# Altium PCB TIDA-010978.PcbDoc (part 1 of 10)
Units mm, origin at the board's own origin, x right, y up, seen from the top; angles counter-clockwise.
Board outline 243.95 x 94.85 mm, 4 copper layers (Top Layer, Mid Layer 1, Mid Layer 2, Bottom Layer), stack 1.623 mm thick; 865 components, 374 nets, 2308 pads, 2132 vias.
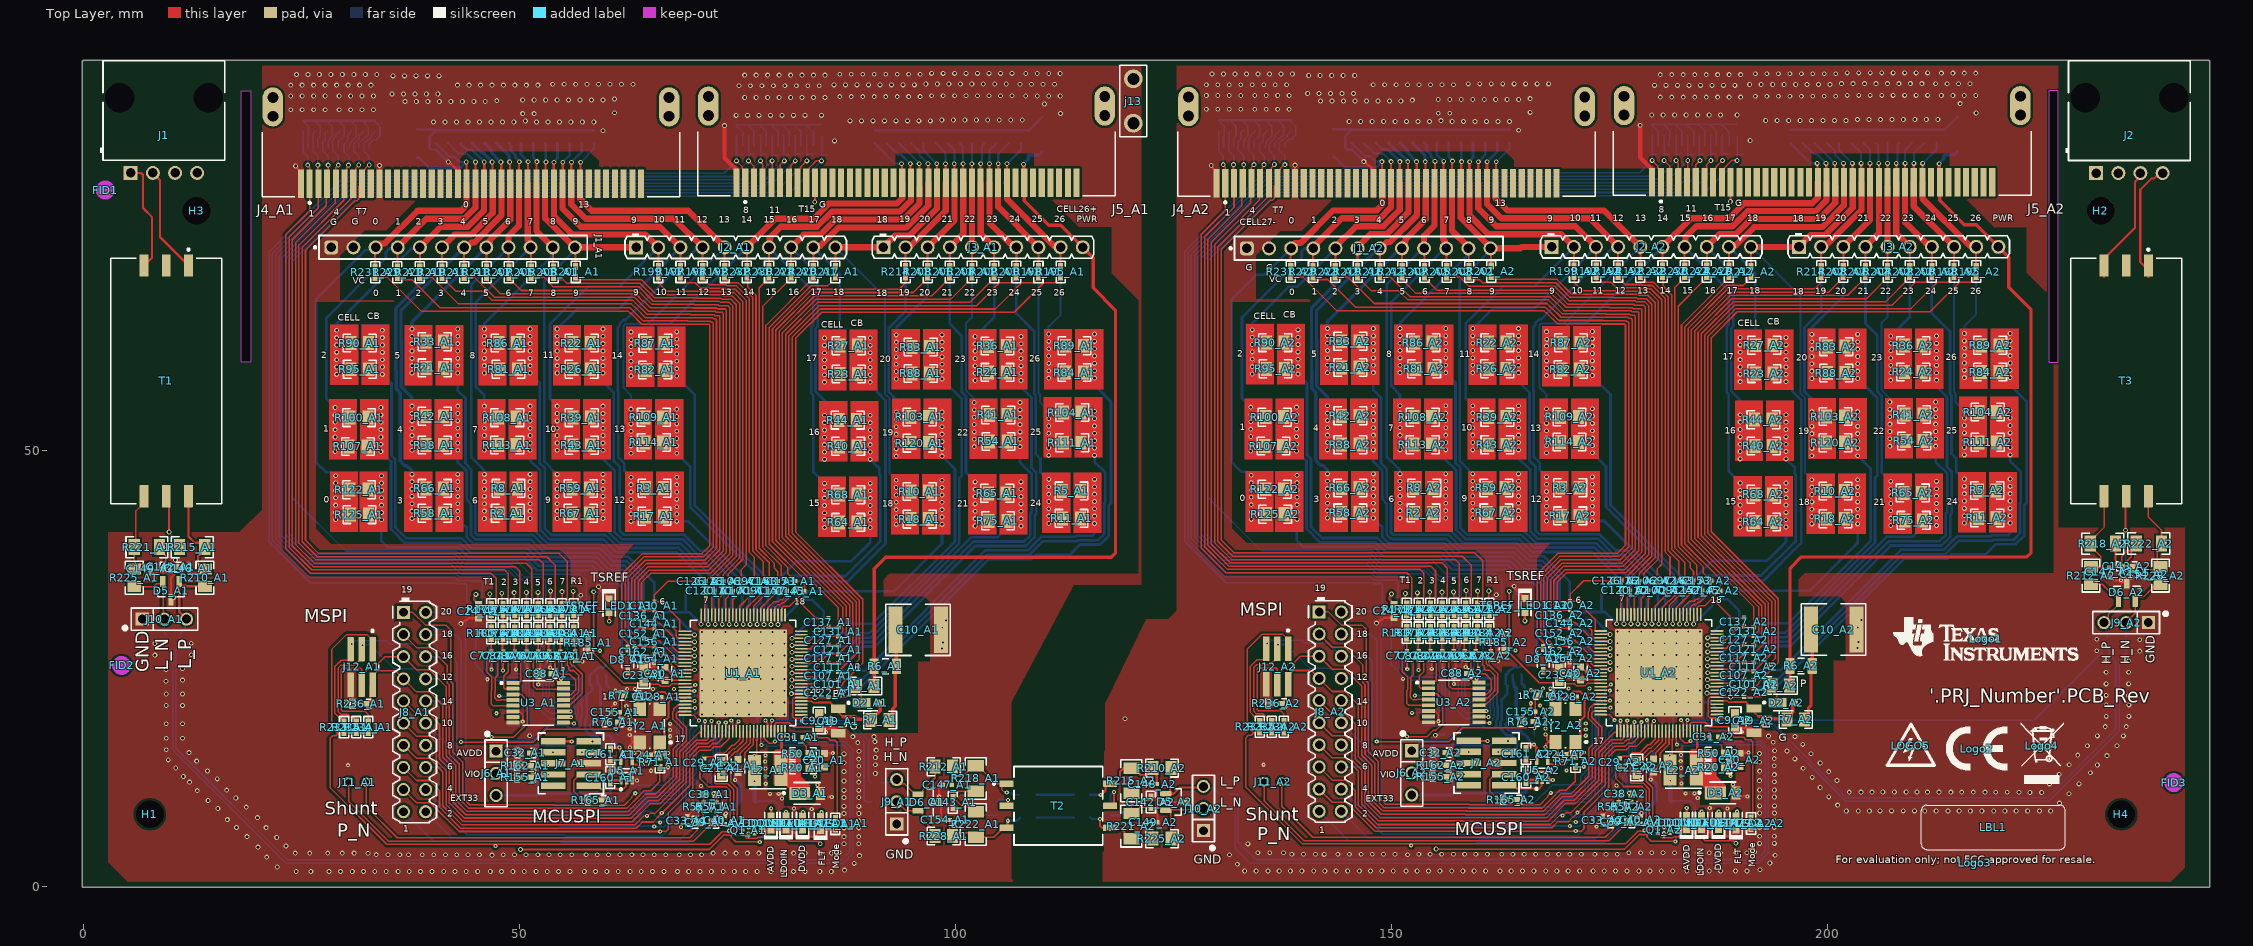
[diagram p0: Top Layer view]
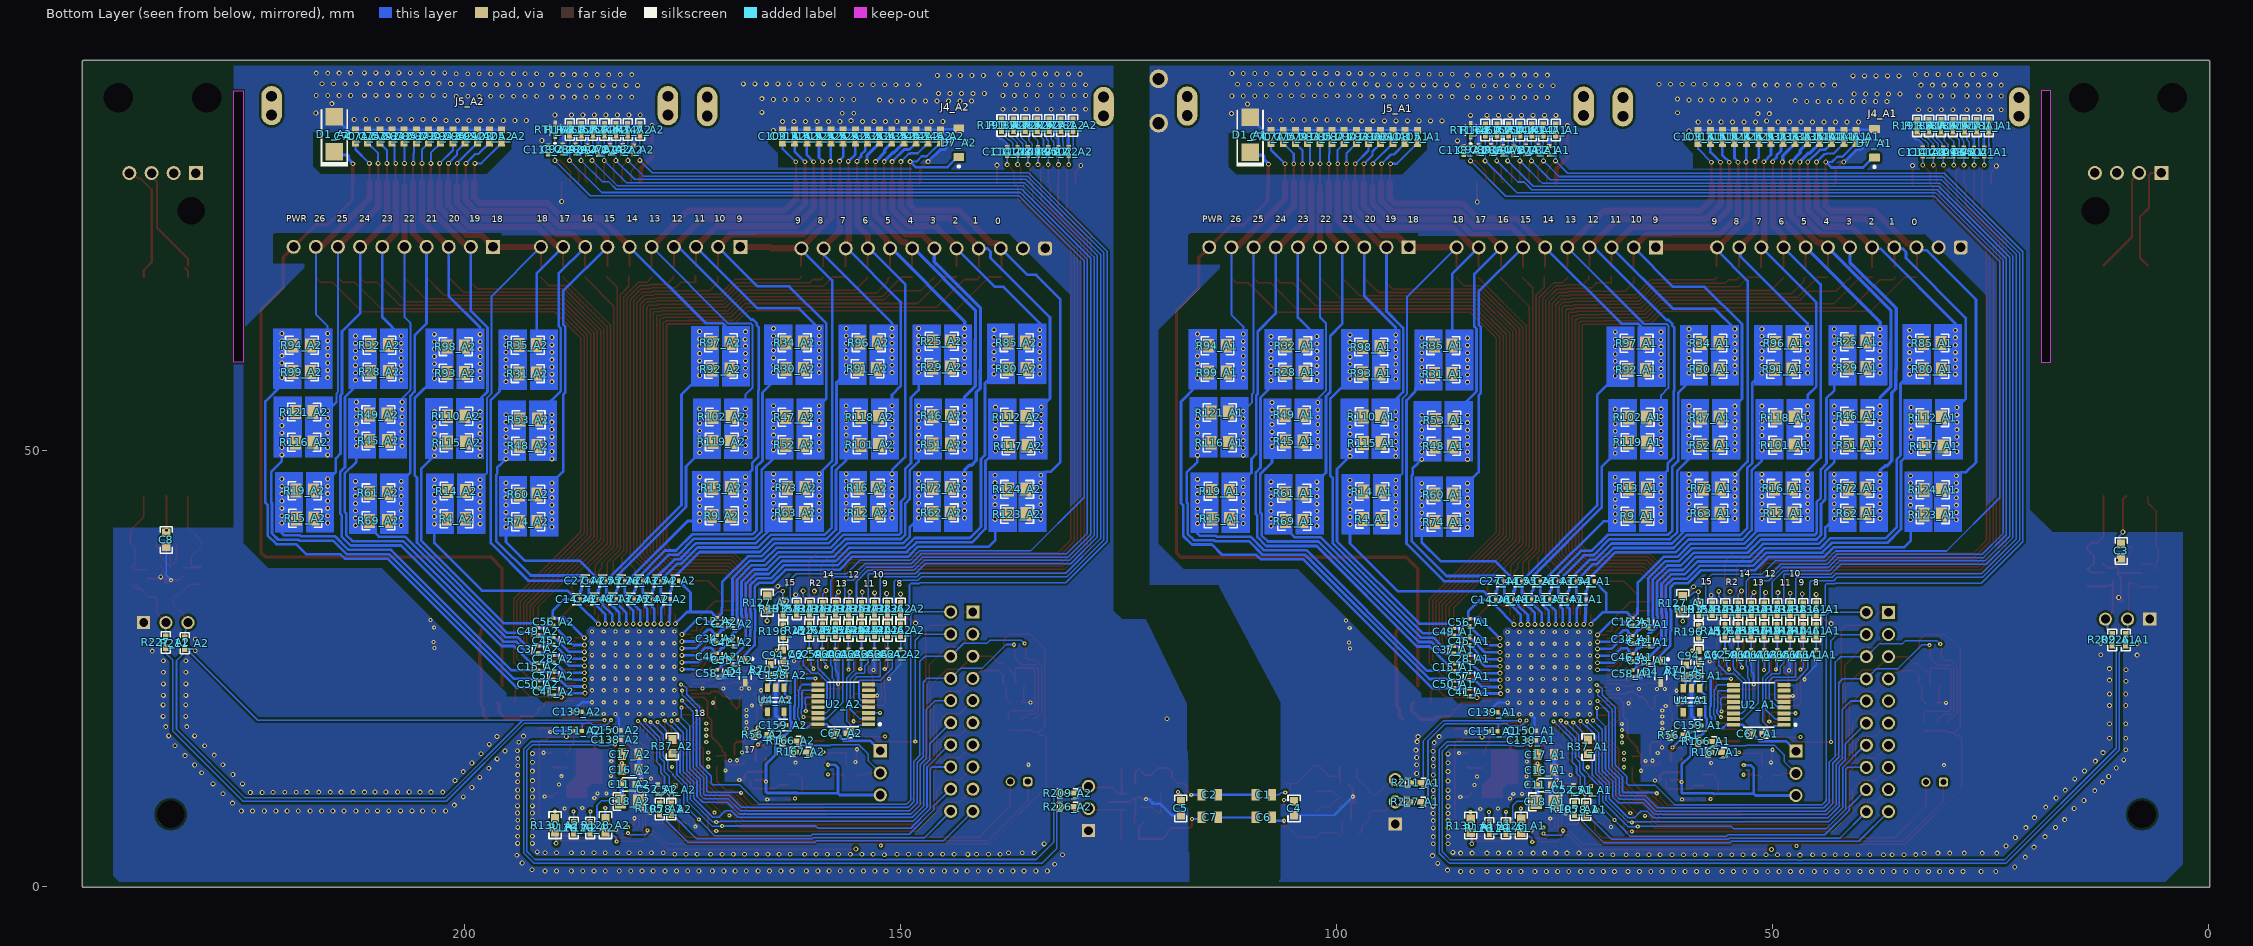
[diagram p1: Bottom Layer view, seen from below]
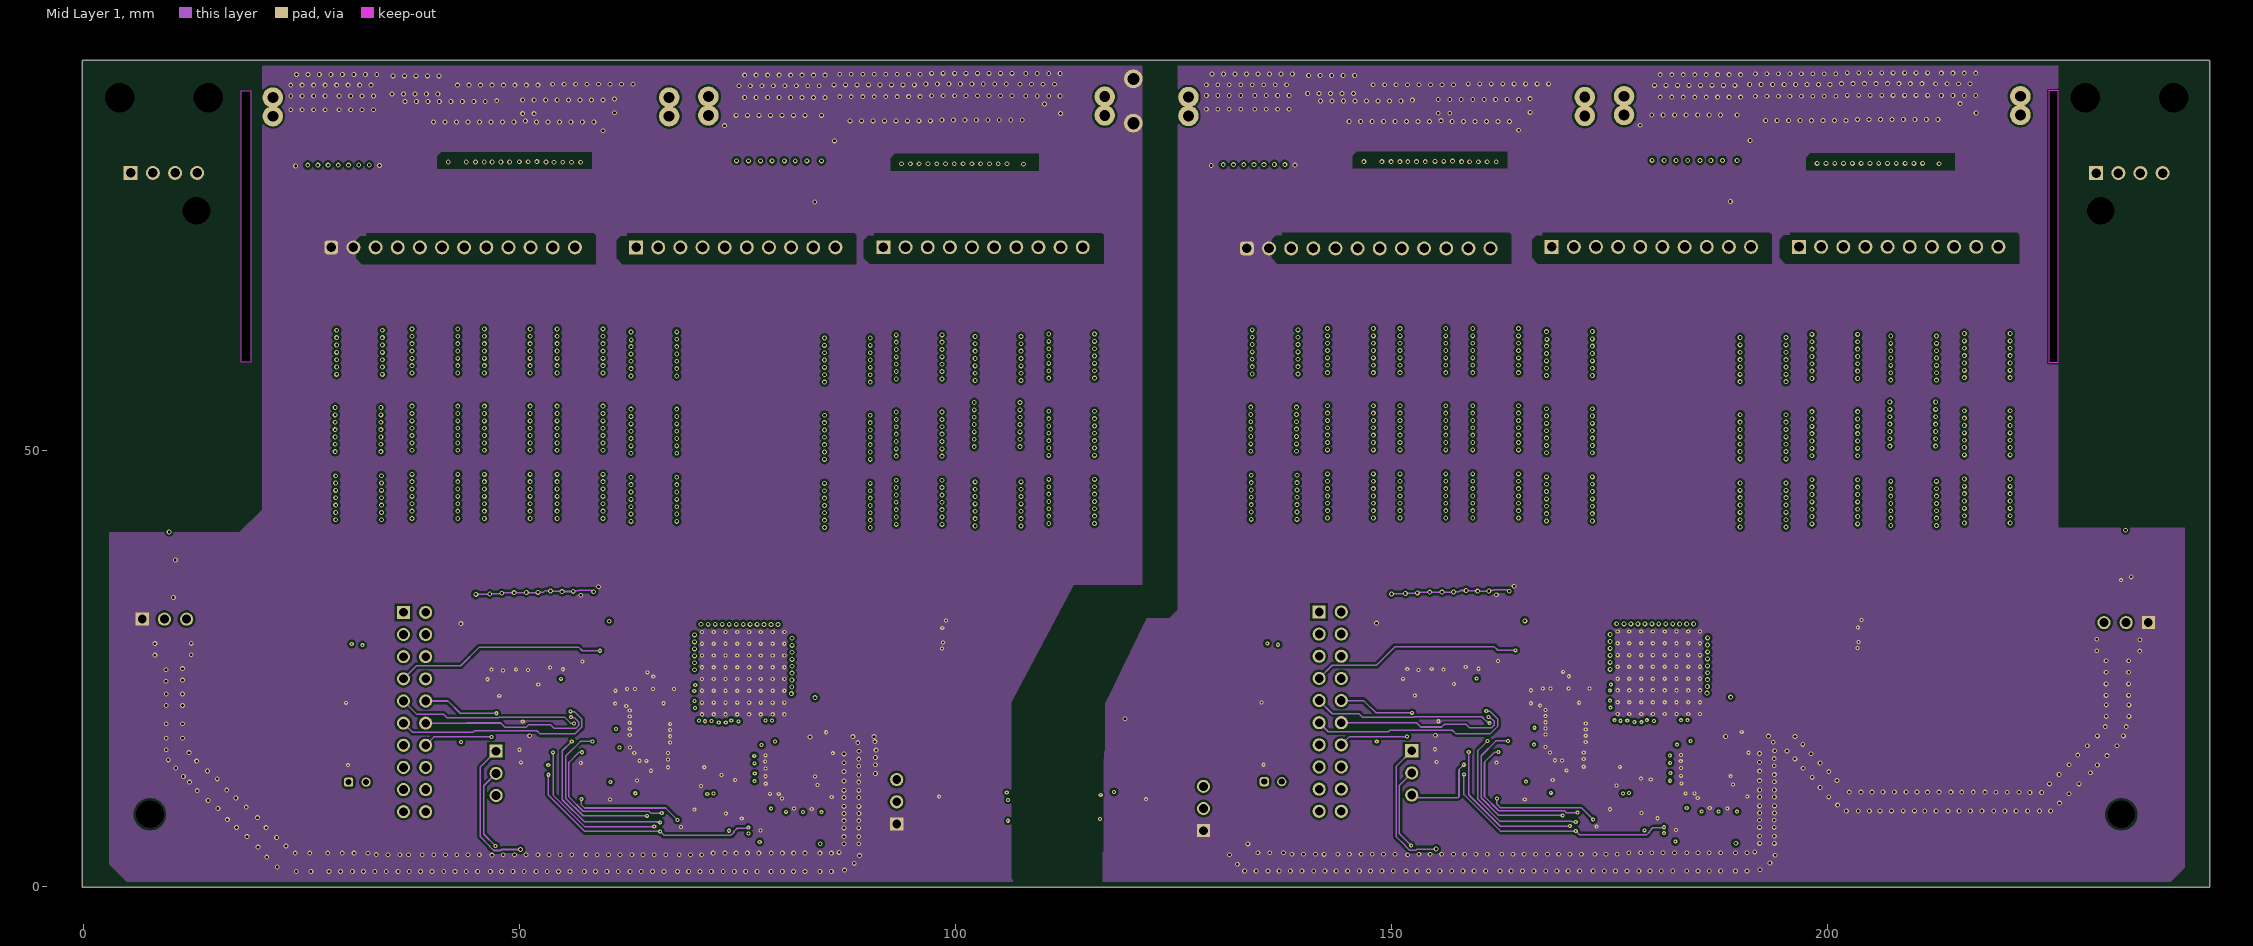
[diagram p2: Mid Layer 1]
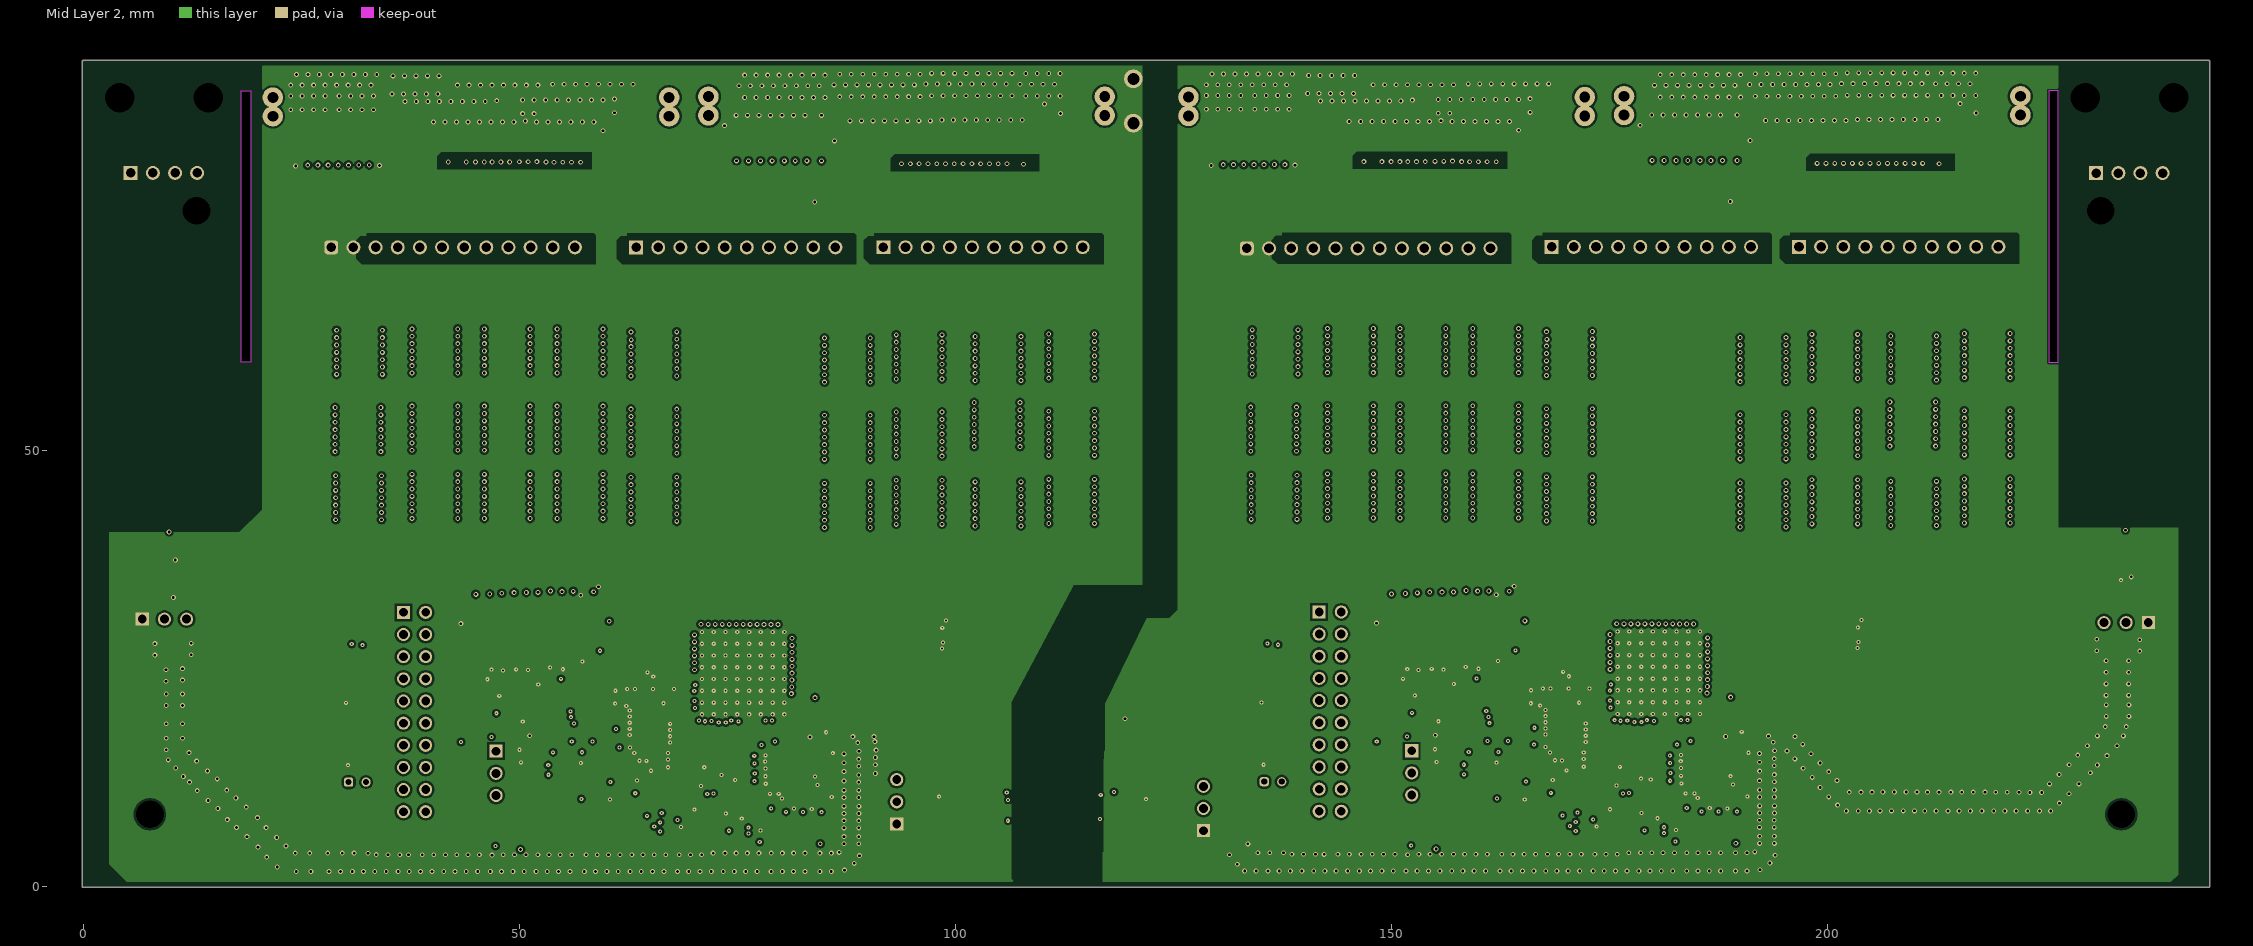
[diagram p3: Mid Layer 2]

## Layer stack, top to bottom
Top Solder: solder mask 0.0102, Solder Resist, Dk 3.5
Top Layer: signal copper 0.07
Dielectric 1: prepreg 0.2032, PP-006, Dk 4.1
Mid Layer 1: signal copper 0.0356
Dielectric1: core 1.0058, FR-4 High Tg, Dk 4.8
Mid Layer 2: signal copper 0.0356
Dielectric 2: prepreg 0.2032, PP-006, Dk 4.1
Bottom Layer: signal copper 0.07
Bottom Solder: solder mask 0.0102, Solder Resist, Dk 3.5

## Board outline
-0.127,0 -0.127,94.6 cw(c0,94.6) 0,94.727 243.7,94.727 cw(c243.7,94.6) 243.827,94.6 243.827,0.007 cw(c243.7,0.007) 243.7,-0.12 0.043,-0.12 cw(c0,0)
cut-out: 225.4,60.1 226.475,60.1 226.475,91.237 225.4,91.237
cut-out: 18.1,60.125 18.1,91.262 19.175,91.262 19.175,60.125

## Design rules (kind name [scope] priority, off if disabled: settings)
AcuteAngle [All] p1: minimum=4.50000000000000E+0001 checktracksonly=FALSE
AssemblyTestPointUsage [All] p1: valid=2
BoardOutlineClearance BoardOutlineClearance_MountingHoles [OnCopper and InComponentClass('Mounting Holes')] p1: gap=1 ignorepadtopadclearanceinfootprint=FALSE
BoardOutlineClearance BoardOutlineClearance_Poly [OnCopper and IsPoly] p2: gap=0.635 ignorepadtopadclearanceinfootprint=FALSE
BoardOutlineClearance [OnCopper and Not InComponentClass('Logo') and not InComponentClass('FiducialMark') and not InRegion(1000,500,4000,800) and not InPoly] p3: gap=1.016 ignorepadtopadclearanceinfootprint=FALSE
Clearance Clearance_Keepouts [((IsTrack Or IsArc) And Not InPoly) And IsFree and IsKeepOut vs ((IsTrack Or IsArc) And Not InPoly) And IsFree and IsKeepOut] p1: gap=0 ignorepadtopadclearanceinfootprint=FALSE
Clearance Clearance_Poly [InPolygon] p2: gap=0.254 ignorepadtopadclearanceinfootprint=TRUE
Clearance Clearance_FiducialMark [IsKeepOut and InComponentClass('FiducialMark') vs IsPad and InComponentClass('FiducialMark')] p3: gap=0 ignorepadtopadclearanceinfootprint=FALSE
Clearance [All] p4: gap=0.2 ignorepadtopadclearanceinfootprint=TRUE
ComponentClearance ComponentClearance_MountingHoles_FiducialMarks [InComponentClass('Mounting Holes') vs InComponentClass('FiducialMark')] p1: gap=1.27 collisioncheckmode=3 verticalgap=0.254 showdistances=FALSE
ComponentClearance ComponentClearance_Shunt [InComponentClass('Header') vs InComponentClass('Shunt')] p2: gap=0 collisioncheckmode=3 verticalgap=0 showdistances=FALSE
ComponentClearance ComponentClearance_Logo [InComponentClass('Logo')] p3: gap=0.762 collisioncheckmode=3 verticalgap=0.254 showdistances=FALSE
ComponentClearance ComponentClearance_ScrewToNut [(HasFootprint('NY PMS 440 0025 PH')) vs (HasFootprint('Keystone_1902C'))] p4: gap=0.127 collisioncheckmode=3 verticalgap=0.254 showdistances=FALSE
ComponentClearance ComponentClearance_MountingHoles [InComponentClass('Mounting Holes')] p5: gap=2.54 collisioncheckmode=3 verticalgap=2540 showdistances=FALSE
ComponentClearance ComponentClearance_SmallPassives [HasFootprint('0201*') or HasFootprint('0402*') or HasFootprint('0508') or HasFootprint('0603*') or HasFootprint('0612') or HasFootprint('0805*') or HasFootprint('0815*') or HasFootprint('0830*') or HasFootprint('1206*') or HasFootprint('1210*') or HasFootprint('1808*') or HasFootprint('1812*') or HasFootprint('1825*') or HasFootprint('2010*') or HasFootprint('2220*') or HasFootprint('2225*') or HasFootprint('2512*') or HasFootprint('2728*') or HasFootprint('3518*') vs HasFootprint('0201*') or HasFootprint('0402*') or HasFootprint('0508') or HasFootprint('0603*') or HasFootprint('0612') or HasFootprint('0805*') or HasFootprint('0815*') or HasFootprint('0830*') or HasFootprint('1206*') or HasFootprint('1210*') or HasFootprint('1808*') or HasFootprint('1812*') or HasFootprint('1825*') or HasFootprint('2010*') or HasFootprint('2220*') or HasFootprint('2225*') or HasFootprint('2512*') or HasFootprint('2728*') or HasFootprint('3518*')] p6: gap=0.38 collisioncheckmode=3 verticalgap=0.254 showdistances=FALSE
ComponentClearance ComponentClearance_THtoSMT [IsThruComponent vs IsSMTComponent] p7: gap=0.762 collisioncheckmode=3 verticalgap=0.762 showdistances=FALSE
ComponentClearance ComponentClearance_THtoTH [IsThruComponent vs IsThruComponent] p8: gap=0.508 collisioncheckmode=3 verticalgap=0.762 showdistances=FALSE
ComponentClearance [All] p9: gap=0.508 collisioncheckmode=3 verticalgap=0.254 showdistances=FALSE
DiffPairsRouting [All] p1: maxlimit=2.54 minlimit=0.254 mostfreqgap=0.254 toplayer_minwidth=0.381 toplayer_maxwidth=0.381 toplayer_prefwidth=0.381 midlayer1_minwidth=0.381 midlayer1_maxwidth=0.381 midlayer1_prefwidth=0.381 midlayer2_minwidth=0.381 midlayer2_maxwidth=0.381 midlayer2_prefwidth=0.381 bottomlayer_minwidth=0.381 bottomlayer_maxwidth=0.381 bottomlayer_prefwidth=0.381 maxuncoupledlength=25.4
FabricationTestPointUsage TestPointUsage [All] p1: valid=2 allowmultiple=FALSE
FabricationTestpoint Testpoint [All] p1: side=3 testpointundercomponent=TRUE minsize=1.016 maxsize=2.54 preferedsize=1.524 minholesize=0 maxholesize=1.016 preferedholesize=0.813 testpointgrid=0.025 allowsidetop=TRUE allowsidebottom=TRUE usegrid=TRUE gridtolerance=0
FanoutControl Fanout_LCC [IsLCC] p1: bgadir=Out bgaviamode=Centered fanoutstyle=Auto fanoutdirection=Alternating viagrid=0.025 // Fanout_LCC (Default Rule)
FanoutControl Fanout_BGA [IsBGA] p2: bgadir=Out bgaviamode=Centered fanoutstyle=Auto fanoutdirection=Alternating viagrid=0.025 // Fanout_BGA (Default Rule)
FanoutControl Fanout_Default [All] p4: bgadir=Out bgaviamode=Centered fanoutstyle=Auto fanoutdirection=Alternating viagrid=0.025 // Fanout_Default (Default Rule)
FanoutControl Fanout_Small [(CompPinCount < 5)] p5: bgadir=Out bgaviamode=Centered fanoutstyle=Auto fanoutdirection=OutThenIn viagrid=0.025 // Fanout_Small (Default Rule)
HoleSize [All] p1: absolutevalues=TRUE maxlimit=6.375 minlimit=0.2 maxpercent=80.000 minpercent=20.000
MinimumAnnularRing MinimumAnnularRing_ThermalPadVias [IsVia and InAnyComponent] p1: minimumring=0.15
MinimumAnnularRing [All] p2: minimumring=0.127
MinimumSolderMaskSliver MinimumSolderMaskSliver_Logo [InComponentClass('Logo') vs InComponentClass('Logo')] p1: minsoldermaskwidth=0.018
MinimumSolderMaskSliver [All] p2: minsoldermaskwidth=0.1
PlaneConnect [All] p1: planeconnectstyle=Relief reliefexpansion=0.254 reliefentries=4 reliefconductorwidth=0.254 reliefairgap=0.254
PolygonConnect [All] p1: connectstyle=Direct reliefconductorwidth=0.254 reliefentries=4 polygonreliefangle="90 Angle" airgapwidth=0.254
RoomDefinition A1 [InComponentClass('A1')] p1: confinementstyle=ConfineIn formatcopy=TRUE lockcomponents=FALSE outline 20.392,97.8 118.05,97.8 118.2,97.95 118.65,97.5 119.1,97.5 119.1,79.005 118.342,78.247 118.342,70.733 121.25,67.825 121.25,35.488 121.199,35.539 104.387,35.539 99.919,31.071 99.919,16.414 101.322,15.011 103.828,15.011 103.75,14.933 103.75,4.466 103.775,4.441 92.902,4.441 88.262,-0.2 13.725,-0.2 13.725,14.912 14.392,15.579 15.214,15.579 15.214,23.583 18.044,26.412 21.298,26.412 21.298,35.994 20.125,37.167 20.125,97.525 20.05,97.6
RoomDefinition A2 [InComponentClass('A2')] p2: confinementstyle=ConfineIn formatcopy=TRUE lockcomponents=FALSE outline 125.392,97.85 223.05,97.85 223.2,98 223.65,97.55 224.1,97.55 224.1,79.055 223.342,78.297 223.342,70.783 226.25,67.875 226.25,35.538 226.199,35.589 209.387,35.589 204.919,31.121 204.919,16.464 206.322,15.061 208.828,15.061 208.75,14.983 208.75,4.516 208.775,4.491 197.902,4.491 193.262,-0.15 118.725,-0.15 118.725,14.962 119.392,15.629 120.214,15.629 120.214,23.633 123.044,26.462 126.298,26.462 126.298,36.044 125.125,37.217 125.125,97.575 125.05,97.65
RoutingVias ThermalPadVias [IsVia and InAnyComponent] p1: holewidth=0.2 width=0.5 viastyle="Through Hole" minholewidth=0.2 minwidth=0.5 maxholewidth=0.33 maxwidth=0.6
RoutingVias [All] p2: holewidth=0.406 width=0.864 viastyle="Through Hole" minholewidth=0.2 minwidth=0.61 maxholewidth=1.016 maxwidth=1.651
SilkToBoardRegionClearance [Not ((IsComment or IsDesignator) And (Hide <> 'False')) and not InRegion(1000,500,4000,800)] p1:
SilkToSilkClearance SilkToSilkClearance_Pb-FreeLogo [(HasFootprint('Pb-Free_Overlay_Medium') OR HasFootprint('Pb-Free_Overlay_Small')) vs (HasFootprint('Pb-Free_Overlay_Medium') OR HasFootprint('Pb-Free_Overlay_Small'))] p1: silktosilkclearance=0
SilkToSilkClearance [All] p2: silktosilkclearance=0.1
SilkToSolderMaskClearance SilkToComponentPadClearance [(IsPad or IsFill or IsRegion) and InAnycomponent] p1: minsilkscreentomaskgap=0.127 clearancetoexposedcopper=TRUE
SilkToSolderMaskClearance "Silk to Solder Mask Opening" [All] p2: minsilkscreentomaskgap=0.1 clearancetoexposedcopper=FALSE
SolderMaskExpansion [All] p1: expansion=0.05 istentingtop=FALSE
SupplyNets "Schematic Supply Nets_1" [InNet('GND_A2')] p1: voltage=0.000
SupplyNets "Schematic Supply Nets" [InNet('GND_A1')] p2: voltage=0.000
UnRoutedNet [All] p1: checkbadconnections=TRUE
Width [All] p1: maxlimit=2.54 minlimit=0.152 preferedwidth=0.254 checkconnectedcopper=TRUE
14 further rules are at their usual default settings.

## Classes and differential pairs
channel class "TIDA-010978 BMU_stack0": A1 A2
component class TIDA-010978: C1 C2 C3 C4 C5 C6 C7 C8 J1 J2 j13 T1 T2 T3
component class Header: J2_A1 J2_A2 J3_A1 J3_A2 J6_A1 J6_A2 J8_A1 J8_A2 J9_A1 J9_A2 J10_A1 J10_A2
component class A2: AVDD_LED1_A2 C9_A2 C10_A2 C11_A2 C12_A2 C13_A2 C14_A2 C15_A2 C16_A2 C17_A2 C18_A2 C19_A2 C20_A2 C21_A2 C22_A2 C23_A2 C24_A2 C25_A2 C26_A2 C27_A2 C28_A2 C29_A2 C30_A2 C31_A2 C32_A2 C33_A2 C34_A2 C35_A2 C36_A2 C37_A2 C38_A2 C39_A2 C40_A2 C41_A2 C42_A2 C43_A2 C44_A2 C45_A2 C46_A2 C47_A2 C48_A2 C49_A2 C50_A2 C51_A2 C52_A2 C53_A2 C54_A2 C55_A2 C56_A2 C57_A2 C58_A2 C59_A2 C60_A2 C61_A2 C62_A2 C63_A2 C64_A2 C65_A2 C66_A2 C67_A2 C68_A2 C69_A2 C70_A2 C71_A2 C72_A2 C73_A2 C74_A2 C75_A2 C76_A2 C77_A2 C78_A2 C79_A2 C80_A2 C81_A2 C82_A2 C83_A2 C84_A2 C85_A2 C86_A2 C87_A2 C88_A2 C89_A2 C90_A2 C91_A2 C92_A2 C93_A2 C94_A2 C95_A2 C96_A2 C97_A2 C98_A2 C99_A2 C100_A2 C101_A2 C102_A2 C103_A2 C104_A2 C105_A2 C106_A2 C107_A2 C108_A2 C109_A2 C110_A2 C111_A2 C112_A2 C113_A2 C114_A2 C115_A2 C116_A2 C117_A2 C118_A2 C119_A2 C120_A2 C121_A2 C122_A2 C123_A2 C124_A2 C125_A2 C126_A2 C127_A2 C128_A2 C129_A2 C130_A2 C131_A2 C132_A2 C133_A2 C134_A2 C135_A2 C136_A2 C137_A2 C138_A2 C139_A2 C140_A2 C141_A2 C142_A2 C143_A2 C144_A2 C145_A2 C146_A2 C147_A2 C148_A2 C149_A2 C150_A2 C151_A2 C152_A2 C153_A2 C154_A2 C155_A2 C156_A2 C157_A2 C158_A2 C159_A2 C160_A2 C161_A2 C162_A2 C163_A2 C164_A2 D1_A2 D2_A2 D3_A2 D4_A2 D5_A2 D6_A2 D7_A2 D8_A2 DVDD_LED1_A2 J1_A2 J2_A2 J3_A2 J4_A2 J5_A2 J6_A2 J7_A2 J8_A2 J9_A2 J10_A2 J11_A2 J12_A2 L2_A2 LDOIN_LED1_A2 NFAULT_LED1_A2 Q1_A2 R1_A2 R2_A2 R3_A2 R4_A2 R5_A2 R6_A2 R7_A2 R8_A2 R9_A2 R10_A2 R11_A2 R12_A2 R13_A2 R14_A2 R15_A2 R16_A2 R17_A2 R18_A2 R19_A2 R20_A2 R21_A2 R22_A2 R23_A2 R24_A2 R25_A2 R26_A2 R27_A2 R28_A2 R29_A2 R30_A2 R31_A2 R32_A2 R33_A2 R34_A2 R35_A2 R36_A2 R37_A2 R38_A2 R39_A2 R40_A2 R41_A2 R42_A2 R43_A2 R44_A2 R45_A2 R46_A2 R47_A2 R48_A2 R49_A2 R50_A2 R51_A2 R52_A2 R53_A2 R54_A2 R55_A2 R56_A2 R57_A2 R58_A2 R59_A2 R60_A2 R61_A2 R62_A2 R63_A2 R64_A2 R65_A2 R66_A2 R67_A2 R68_A2 R69_A2 R70_A2 R71_A2 R72_A2 R73_A2 R74_A2 R75_A2 R76_A2 R77_A2 R78_A2 R79_A2 R80_A2 R81_A2 R82_A2 R83_A2 R84_A2 R85_A2 R86_A2 R87_A2 R88_A2 R89_A2 R90_A2 R91_A2 R92_A2 R93_A2 R94_A2 R95_A2 R96_A2 R97_A2 R98_A2 R99_A2 R100_A2 R101_A2 R102_A2 R103_A2 R104_A2 R105_A2 R107_A2 R108_A2 R109_A2 R110_A2 R111_A2 R112_A2 R113_A2 R114_A2 R115_A2 R116_A2 R117_A2 R118_A2 R119_A2 R120_A2 R121_A2 R122_A2 R123_A2 R124_A2 R125_A2 R126_A2 R127_A2 R128_A2 R129_A2 R130_A2 R131_A2 R132_A2 R133_A2 R134_A2 R135_A2 R136_A2 R137_A2 R138_A2 R140_A2 R141_A2 R143_A2 R144_A2 R146_A2 R147_A2 R149_A2 R150_A2 R152_A2 R153_A2 R155_A2 R156_A2 R157_A2 R159_A2 R160_A2 R162_A2 R163_A2 R164_A2 R165_A2 R166_A2 R167_A2 R168_A2 R169_A2 R170_A2 R171_A2 R172_A2 R173_A2 R174_A2 R175_A2 R176_A2 R177_A2 R178_A2 R179_A2 R180_A2 R181_A2 R182_A2 R183_A2 R184_A2 R185_A2 R186_A2 R187_A2 R188_A2 R189_A2 R190_A2 R191_A2 R192_A2 R193_A2 R194_A2 R195_A2 R196_A2 R197_A2 R198_A2 R199_A2 R200_A2 R201_A2 R202_A2 R203_A2 R204_A2 R205_A2 R206_A2 R207_A2 R208_A2 R209_A2 R210_A2 R211_A2 R212_A2 R213_A2 R214_A2 R215_A2 R216_A2 R217_A2 R218_A2 R219_A2 R220_A2 R221_A2 R222_A2 R223_A2 R224_A2 R225_A2 R226_A2 R227_A2 R228_A2 R229_A2 R230_A2 R231_A2 R232_A2 R233_A2 R234_A2 R235_A2 R236_A2 RT1_A2 TSREF_LED1_A2 U1_A2 U2_A2 U3_A2 U4_A2 U5_A2 Y2_A2
component class A1: AVDD_LED1_A1 C9_A1 C10_A1 C11_A1 C12_A1 C13_A1 C14_A1 C15_A1 C16_A1 C17_A1 C18_A1 C19_A1 C20_A1 C21_A1 C22_A1 C23_A1 C24_A1 C25_A1 C26_A1 C27_A1 C28_A1 C29_A1 C30_A1 C31_A1 C32_A1 C33_A1 C34_A1 C35_A1 C36_A1 C37_A1 C38_A1 C39_A1 C40_A1 C41_A1 C42_A1 C43_A1 C44_A1 C45_A1 C46_A1 C47_A1 C48_A1 C49_A1 C50_A1 C51_A1 C52_A1 C53_A1 C54_A1 C55_A1 C56_A1 C57_A1 C58_A1 C59_A1 C60_A1 C61_A1 C62_A1 C63_A1 C64_A1 C65_A1 C66_A1 C67_A1 C68_A1 C69_A1 C70_A1 C71_A1 C72_A1 C73_A1 C74_A1 C75_A1 C76_A1 C77_A1 C78_A1 C79_A1 C80_A1 C81_A1 C82_A1 C83_A1 C84_A1 C85_A1 C86_A1 C87_A1 C88_A1 C89_A1 C90_A1 C91_A1 C92_A1 C93_A1 C94_A1 C95_A1 C96_A1 C97_A1 C98_A1 C99_A1 C100_A1 C101_A1 C102_A1 C103_A1 C104_A1 C105_A1 C106_A1 C107_A1 C108_A1 C109_A1 C110_A1 C111_A1 C112_A1 C113_A1 C114_A1 C115_A1 C116_A1 C117_A1 C118_A1 C119_A1 C120_A1 C121_A1 C122_A1 C123_A1 C124_A1 C125_A1 C126_A1 C127_A1 C128_A1 C129_A1 C130_A1 C131_A1 C132_A1 C133_A1 C134_A1 C135_A1 C136_A1 C137_A1 C138_A1 C139_A1 C140_A1 C141_A1 C142_A1 C143_A1 C144_A1 C145_A1 C146_A1 C147_A1 C148_A1 C149_A1 C150_A1 C151_A1 C152_A1 C153_A1 C154_A1 C155_A1 C156_A1 C157_A1 C158_A1 C159_A1 C160_A1 C161_A1 C162_A1 C163_A1 C164_A1 D1_A1 D2_A1 D3_A1 D4_A1 D5_A1 D6_A1 D7_A1 D8_A1 DVDD_LED1_A1 J1_A1 J2_A1 J3_A1 J4_A1 J5_A1 J6_A1 J7_A1 J8_A1 J9_A1 J10_A1 J11_A1 J12_A1 L2_A1 LDOIN_LED1_A1 NFAULT_LED1_A1 Q1_A1 R1_A1 R2_A1 R3_A1 R4_A1 R5_A1 R6_A1 R7_A1 R8_A1 R9_A1 R10_A1 R11_A1 R12_A1 R13_A1 R14_A1 R15_A1 R16_A1 R17_A1 R18_A1 R19_A1 R20_A1 R21_A1 R22_A1 R23_A1 R24_A1 R25_A1 R26_A1 R27_A1 R28_A1 R29_A1 R30_A1 R31_A1 R32_A1 R33_A1 R34_A1 R35_A1 R36_A1 R37_A1 R38_A1 R39_A1 R40_A1 R41_A1 R42_A1 R43_A1 R44_A1 R45_A1 R46_A1 R47_A1 R48_A1 R49_A1 R50_A1 R51_A1 R52_A1 R53_A1 R54_A1 R55_A1 R56_A1 R57_A1 R58_A1 R59_A1 R60_A1 R61_A1 R62_A1 R63_A1 R64_A1 R65_A1 R66_A1 R67_A1 R68_A1 R69_A1 R70_A1 R71_A1 R72_A1 R73_A1 R74_A1 R75_A1 R76_A1 R77_A1 R78_A1 R79_A1 R80_A1 R81_A1 R82_A1 R83_A1 R84_A1 R85_A1 R86_A1 R87_A1 R88_A1 R89_A1 R90_A1 R91_A1 R92_A1 R93_A1 R94_A1 R95_A1 R96_A1 R97_A1 R98_A1 R99_A1 R100_A1 R101_A1 R102_A1 R103_A1 R104_A1 R105_A1 R107_A1 R108_A1 R109_A1 R110_A1 R111_A1 R112_A1 R113_A1 R114_A1 R115_A1 R116_A1 R117_A1 R118_A1 R119_A1 R120_A1 R121_A1 R122_A1 R123_A1 R124_A1 R125_A1 R126_A1 R127_A1 R128_A1 R129_A1 R130_A1 R131_A1 R132_A1 R133_A1 R134_A1 R135_A1 R136_A1 R137_A1 R138_A1 R140_A1 R141_A1 R143_A1 R144_A1 R146_A1 R147_A1 R149_A1 R150_A1 R152_A1 R153_A1 R155_A1 R156_A1 R157_A1 R159_A1 R160_A1 R162_A1 R163_A1 R164_A1 R165_A1 R166_A1 R167_A1 R168_A1 R169_A1 R170_A1 R171_A1 R172_A1 R173_A1 R174_A1 R175_A1 R176_A1 R177_A1 R178_A1 R179_A1 R180_A1 R181_A1 R182_A1 R183_A1 R184_A1 R185_A1 R186_A1 R187_A1 R188_A1 R189_A1 R190_A1 R191_A1 R192_A1 R193_A1 R194_A1 R195_A1 R196_A1 R197_A1 R198_A1 R199_A1 R200_A1 R201_A1 R202_A1 R203_A1 R204_A1 R205_A1 R206_A1 R207_A1 R208_A1 R209_A1 R210_A1 R211_A1 R212_A1 R213_A1 R214_A1 R215_A1 R216_A1 R217_A1 R218_A1 R219_A1 R220_A1 R221_A1 R222_A1 R223_A1 R224_A1 R225_A1 R226_A1 R227_A1 R228_A1 R229_A1 R230_A1 R231_A1 R232_A1 R233_A1 R234_A1 R235_A1 R236_A1 RT1_A1 TSREF_LED1_A1 U1_A1 U2_A1 U3_A1 U4_A1 U5_A1 Y2_A1
component class Label: LBL1
component class AssemblyNote: ZZ1 ZZ2 ZZ3 ZZ4
component class FiducialMark: FID1 FID2 FID3
component class U_TIDA-010978_Hardware: FID1 FID2 FID3 H1 H2 H3 H4 LBL1 Logo1 Logo2 Logo3 Logo4 LOGO5 ZZ1 ZZ2 ZZ3 ZZ4
component class Logo: Logo1

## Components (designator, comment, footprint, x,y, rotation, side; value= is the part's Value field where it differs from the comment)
AVDD_LED1_A1 "150060GS75000" WL-SMCW_GREEN 78.832,7.262 r90 top value=Green (schematic designator AVDD_LED1)
AVDD_LED1_A2 "150060GS75000" WL-SMCW_GREEN 183.832,7.313 r90 top value=Green (schematic designator AVDD_LED1)
C1 "885342207006" WCAP-CSMH_0805_L2W1.25H1.25 108.341,10.497 r0 bottom
C2 "885342207006" WCAP-CSMH_0805_L2W1.25H1.25 114.516,10.497 r0 bottom
C3 "GCM1885C1H101JA16J" 0603 10.033,38.463 r90 bottom value=100pF
C4 "GCM1885C1H101JA16J" 0603 104.875,8.946 r90 bottom value=100pF
C5 "GCM1885C1H101JA16J" 0603 117.849,8.946 r90 bottom value=100pF
C6 "885342207006" WCAP-CSMH_0805_L2W1.25H1.25 108.341,7.915 r0 bottom
C7 "885342207006" WCAP-CSMH_0805_L2W1.25H1.25 114.516,7.915 r0 bottom
C8 "GCM1885C1H101JA16J" 0603 234.192,39.74 r90 bottom value=100pF
C9_A1 "C0603C103K2RACTU" 0603 84.393,19.014 r90 top value=0.01uF (schematic designator C9)
C9_A2 "C0603C103K2RACTU" 0603 189.393,19.064 r90 top value=0.01uF (schematic designator C9)
C10_A1 "CGA9N3X7R2E105K230KE" 2220_280 95.719,29.417 r0 top value=1uF (schematic designator C10)
C10_A2 "CGA9N3X7R2E105K230KE" 2220_280 200.704,29.452 r0 top value=1uF (schematic designator C10)
C11_A1 "885012206050" FP-885012206050_0603-MFG 76.089,11.652 r0 bottom value=470nF (schematic designator C11)
C11_A2 "885012206050" FP-885012206050_0603-MFG 181.089,11.702 r0 bottom value=470nF (schematic designator C11)
C12_A1 "GRM155C81C105KE11D" FP-GRM155C81C105KE11D_0402-MFG 66.054,30.365 r90 bottom value=1µF (schematic designator C12)
C12_A2 "GRM155C81C105KE11D" FP-GRM155C81C105KE11D_0402-MFG 171.054,30.415 r90 bottom value=1µF (schematic designator C12)
C13_A1 "GRM155C81C105KE11D" FP-GRM155C81C105KE11D_0402-MFG 75.938,32.907 r0 bottom value=1µF (schematic designator C13)
C13_A2 "GRM155C81C105KE11D" FP-GRM155C81C105KE11D_0402-MFG 180.938,32.957 r0 bottom value=1µF (schematic designator C13)
C14_A1 "GRM155C81C105KE11D" FP-GRM155C81C105KE11D_0402-MFG 82.119,32.884 r0 bottom value=1µF (schematic designator C14)
C14_A2 "GRM155C81C105KE11D" FP-GRM155C81C105KE11D_0402-MFG 187.119,32.934 r0 bottom value=1µF (schematic designator C14)
C15_A1 "GRM155C81C105KE11D" FP-GRM155C81C105KE11D_0402-MFG 86.559,25.123 r270 bottom value=1µF (schematic designator C15)
C15_A2 "GRM155C81C105KE11D" FP-GRM155C81C105KE11D_0402-MFG 191.559,25.173 r270 bottom value=1µF (schematic designator C15)
C16_A1 "885012107014" WCAP-CSGP_0805_L2W1.25H1.25 75.994,13.345 r0 bottom (schematic designator C16)
C16_A2 "885012107014" WCAP-CSGP_0805_L2W1.25H1.25 180.994,13.395 r0 bottom (schematic designator C16)
C17_A1 "885012107014" WCAP-CSGP_0805_L2W1.25H1.25 75.994,15.117 r0 bottom (schematic designator C17)
C17_A2 "885012107014" WCAP-CSGP_0805_L2W1.25H1.25 180.994,15.167 r0 bottom (schematic designator C17)
C18_A1 "DNP" 0805_HV 76.08,9.691 r180 bottom value=10uF (schematic designator C18)
C18_A2 "DNP" 0805_HV 181.08,9.741 r180 bottom value=10uF (schematic designator C18)
C19_A1 "C1206C154KARACAUTO" FP-C1206C-EB-MFG 86.559,18.953 r90 top value="0.15 μF" (schematic designator C19)
C19_A2 "C1206C154KARACAUTO" FP-C1206C-EB-MFG 191.559,19.003 r90 top value="0.15 μF" (schematic designator C19)
C20_A1 "DNP" WCAP-CSMH_0603_L1.6W0.8H0.8_Reflow 84.958,14.465 r270 top (schematic designator C20)
C20_A2 "DNP" WCAP-CSMH_0603_L1.6W0.8H0.8_Reflow 189.958,14.515 r270 top (schematic designator C20)
C21_A1 "885012206076" 0603 73.142,13.565 r90 top value=1uF (schematic designator C21)
C21_A2 "885012206076" 0603 178.142,13.615 r90 top value=1uF (schematic designator C21)
C22_A1 "885012206050" FP-885012206050_0603-MFG 75.044,13.807 r90 top value=470nF (schematic designator C22)
C22_A2 "885012206050" FP-885012206050_0603-MFG 180.044,13.857 r90 top value=470nF (schematic designator C22)
C23_A1 "885012206076" 0603 64.246,24.236 r270 top value=1uF (schematic designator C23)
C23_A2 "885012206076" 0603 169.246,24.286 r270 top value=1uF (schematic designator C23)
C24_A1 "885012206089" WCAP-CSGP_0603_L1.6W0.8H0.8_Reflow 45.296,31.553 r90 top (schematic designator C24)
C24_A2 "885012206089" WCAP-CSGP_0603_L1.6W0.8H0.8_Reflow 150.296,31.603 r90 top (schematic designator C24)
C25_A1 "GRM155C81C105KE11D" FP-GRM155C81C105KE11D_0402-MFG 64.272,30.05 r90 bottom value=1µF (schematic designator C25)
C25_A2 "GRM155C81C105KE11D" FP-GRM155C81C105KE11D_0402-MFG 169.272,30.1 r90 bottom value=1µF (schematic designator C25)
C26_A1 "GRM155C81C105KE11D" FP-GRM155C81C105KE11D_0402-MFG 74.956,34.979 r0 bottom value=1µF (schematic designator C26)
C26_A2 "GRM155C81C105KE11D" FP-GRM155C81C105KE11D_0402-MFG 179.956,35.029 r0 bottom value=1µF (schematic designator C26)
C27_A1 "GRM155C81C105KE11D" FP-GRM155C81C105KE11D_0402-MFG 81.161,34.999 r0 bottom value=1µF (schematic designator C27)
C27_A2 "GRM155C81C105KE11D" FP-GRM155C81C105KE11D_0402-MFG 186.161,35.049 r0 bottom value=1µF (schematic designator C27)
C28_A1 "GRM155C81C105KE11D" FP-GRM155C81C105KE11D_0402-MFG 84.805,26.077 r270 bottom value=1µF (schematic designator C28)
C28_A2 "GRM155C81C105KE11D" FP-GRM155C81C105KE11D_0402-MFG 189.805,26.127 r270 bottom value=1µF (schematic designator C28)
C29_A1 "885012205092" WCAP-CSGP_0402_L1W0.5H0.5 71.19,14.16 r90 top (schematic designator C29)
C29_A2 "885012205092" WCAP-CSGP_0402_L1W0.5H0.5 176.19,14.21 r90 top (schematic designator C29)
C30_A1 "885012206050" FP-885012206050_0603-MFG 66.704,24.379 r90 top value=470nF (schematic designator C30)
C30_A2 "885012206050" FP-885012206050_0603-MFG 171.704,24.429 r90 top value=470nF (schematic designator C30)
C31_A1 "885012205067" WCAP-CSGP_0402_L1W0.5H0.5 81.984,17.092 r180 top (schematic designator C31)
C31_A2 "885012205067" WCAP-CSGP_0402_L1W0.5H0.5 186.984,17.142 r180 top (schematic designator C31)
C32_A1 "DNP" 0402 50.671,15.296 r180 top value=47pF (schematic designator C32)
C32_A2 "DNP" 0402 155.671,15.346 r180 top value=47pF (schematic designator C32)
C33_A1 "885012205092" WCAP-CSGP_0402_L1W0.5H0.5 69.229,7.539 r90 top (schematic designator C33)
C33_A2 "885012205092" WCAP-CSGP_0402_L1W0.5H0.5 174.229,7.589 r90 top (schematic designator C33)
C34_A1 "GRM155C81C105KE11D" FP-GRM155C81C105KE11D_0402-MFG 66.085,28.324 r90 bottom value=1µF (schematic designator C34)
C34_A2 "GRM155C81C105KE11D" FP-GRM155C81C105KE11D_0402-MFG 171.085,28.374 r90 bottom value=1µF (schematic designator C34)
C35_A1 "GRM155C81C105KE11D" FP-GRM155C81C105KE11D_0402-MFG 73.876,32.9 r0 bottom value=1µF (schematic designator C35)
C35_A2 "GRM155C81C105KE11D" FP-GRM155C81C105KE11D_0402-MFG 178.876,32.95 r0 bottom value=1µF (schematic designator C35)
C36_A1 "GRM155C81C105KE11D" FP-GRM155C81C105KE11D_0402-MFG 80.068,32.908 r0 bottom value=1µF (schematic designator C36)
C36_A2 "GRM155C81C105KE11D" FP-GRM155C81C105KE11D_0402-MFG 185.068,32.958 r0 bottom value=1µF (schematic designator C36)
C37_A1 "GRM155C81C105KE11D" FP-GRM155C81C105KE11D_0402-MFG 86.559,27.118 r270 bottom value=1µF (schematic designator C37)
C37_A2 "GRM155C81C105KE11D" FP-GRM155C81C105KE11D_0402-MFG 191.559,27.168 r270 bottom value=1µF (schematic designator C37)
C38_A1 "885012206072" WCAP-CSGP_0603_L1.6W0.8H0.8_Reflow 71.812,10.548 r0 top (schematic designator C38)
C38_A2 "885012206072" WCAP-CSGP_0603_L1.6W0.8H0.8_Reflow 176.812,10.598 r0 top (schematic designator C38)
C39_A1 "DNP" 0603 71.351,7.351 r0 top value=1uF (schematic designator C39)
C39_A2 "DNP" 0603 176.351,7.401 r0 top value=1uF (schematic designator C39)
C40_A1 "885012205092" WCAP-CSGP_0402_L1W0.5H0.5 73.567,7.612 r270 top (schematic designator C40)
C40_A2 "885012205092" WCAP-CSGP_0402_L1W0.5H0.5 178.567,7.662 r270 top (schematic designator C40)
C41_A1 "GRM155C81C105KE11D" FP-GRM155C81C105KE11D_0402-MFG 84.775,22.263 r270 bottom value=1µF (schematic designator C41)
C41_A2 "GRM155C81C105KE11D" FP-GRM155C81C105KE11D_0402-MFG 189.775,22.313 r270 bottom value=1µF (schematic designator C41)
C42_A1 "GRM155C81C105KE11D" FP-GRM155C81C105KE11D_0402-MFG 64.272,27.972 r90 bottom value=1µF (schematic designator C42)
C42_A2 "GRM155C81C105KE11D" FP-GRM155C81C105KE11D_0402-MFG 169.272,28.022 r90 bottom value=1µF (schematic designator C42)
C43_A1 "GRM155C81C105KE11D" FP-GRM155C81C105KE11D_0402-MFG 72.894,34.974 r0 bottom value=1µF (schematic designator C43)
C43_A2 "GRM155C81C105KE11D" FP-GRM155C81C105KE11D_0402-MFG 177.894,35.024 r0 bottom value=1µF (schematic designator C43)
C44_A1 "GRM155C81C105KE11D" FP-GRM155C81C105KE11D_0402-MFG 79.134,34.986 r0 bottom value=1µF (schematic designator C44)
C44_A2 "GRM155C81C105KE11D" FP-GRM155C81C105KE11D_0402-MFG 184.134,35.036 r0 bottom value=1µF (schematic designator C44)
C45_A1 "GRM155C81C105KE11D" FP-GRM155C81C105KE11D_0402-MFG 84.8,28.126 r270 bottom value=1µF (schematic designator C45)
C45_A2 "GRM155C81C105KE11D" FP-GRM155C81C105KE11D_0402-MFG 189.8,28.176 r270 bottom value=1µF (schematic designator C45)
C46_A1 "GRM155C81C105KE11D" FP-GRM155C81C105KE11D_0402-MFG 66.085,26.271 r90 bottom value=1µF (schematic designator C46)
C46_A2 "GRM155C81C105KE11D" FP-GRM155C81C105KE11D_0402-MFG 171.085,26.321 r90 bottom value=1µF (schematic designator C46)
C47_A1 "GRM155C81C105KE11D" FP-GRM155C81C105KE11D_0402-MFG 71.785,32.905 r0 bottom value=1µF (schematic designator C47)
C47_A2 "GRM155C81C105KE11D" FP-GRM155C81C105KE11D_0402-MFG 176.785,32.955 r0 bottom value=1µF (schematic designator C47)
C48_A1 "GRM155C81C105KE11D" FP-GRM155C81C105KE11D_0402-MFG 78.015,32.908 r0 bottom value=1µF (schematic designator C48)
C48_A2 "GRM155C81C105KE11D" FP-GRM155C81C105KE11D_0402-MFG 183.015,32.958 r0 bottom value=1µF (schematic designator C48)
C49_A1 "GRM155C81C105KE11D" FP-GRM155C81C105KE11D_0402-MFG 86.559,29.183 r270 bottom value=1µF (schematic designator C49)
C49_A2 "GRM155C81C105KE11D" FP-GRM155C81C105KE11D_0402-MFG 191.559,29.233 r270 bottom value=1µF (schematic designator C49)
C50_A1 "GRM155C81C105KE11D" FP-GRM155C81C105KE11D_0402-MFG 86.559,23.153 r270 bottom value=1µF (schematic designator C50)
C50_A2 "GRM155C81C105KE11D" FP-GRM155C81C105KE11D_0402-MFG 191.559,23.203 r270 bottom value=1µF (schematic designator C50)
C51_A1 "885012205092" WCAP-CSGP_0402_L1W0.5H0.5 70.819,11.009 r90 bottom (schematic designator C51)
C51_A2 "885012205092" WCAP-CSGP_0402_L1W0.5H0.5 175.819,11.059 r90 bottom (schematic designator C51)
C52_A1 "885012205092" WCAP-CSGP_0402_L1W0.5H0.5 72.854,11.085 r270 bottom (schematic designator C52)
C52_A2 "885012205092" WCAP-CSGP_0402_L1W0.5H0.5 177.854,11.135 r270 bottom (schematic designator C52)
C53_A1 "GRM155C81C105KE11D" FP-GRM155C81C105KE11D_0402-MFG 64.272,25.893 r90 bottom value=1µF (schematic designator C53)
C53_A2 "GRM155C81C105KE11D" FP-GRM155C81C105KE11D_0402-MFG 169.272,25.943 r90 bottom value=1µF (schematic designator C53)
C54_A1 "GRM155C81C105KE11D" FP-GRM155C81C105KE11D_0402-MFG 70.833,34.999 r0 bottom value=1µF (schematic designator C54)
C54_A2 "GRM155C81C105KE11D" FP-GRM155C81C105KE11D_0402-MFG 175.833,35.049 r0 bottom value=1µF (schematic designator C54)
C55_A1 "GRM155C81C105KE11D" FP-GRM155C81C105KE11D_0402-MFG 77.031,34.984 r0 bottom value=1µF (schematic designator C55)
C55_A2 "GRM155C81C105KE11D" FP-GRM155C81C105KE11D_0402-MFG 182.031,35.034 r0 bottom value=1µF (schematic designator C55)
C56_A1 "GRM155C81C105KE11D" FP-GRM155C81C105KE11D_0402-MFG 84.793,30.287 r270 bottom value=1µF (schematic designator C56)
C56_A2 "GRM155C81C105KE11D" FP-GRM155C81C105KE11D_0402-MFG 189.793,30.337 r270 bottom value=1µF (schematic designator C56)
C57_A1 "GRM155C81C105KE11D" FP-GRM155C81C105KE11D_0402-MFG 84.805,24.082 r270 bottom value=1µF (schematic designator C57)
C57_A2 "GRM155C81C105KE11D" FP-GRM155C81C105KE11D_0402-MFG 189.805,24.132 r270 bottom value=1µF (schematic designator C57)
C58_A1 "GRM155C81C105KE11D" FP-GRM155C81C105KE11D_0402-MFG 66.054,24.379 r90 bottom value=1µF (schematic designator C58)
C58_A2 "GRM155C81C105KE11D" FP-GRM155C81C105KE11D_0402-MFG 171.054,24.429 r90 bottom value=1µF (schematic designator C58)
C59_A1 "885012205086" WCAP-CSGP_0402_L1W0.5H0.5 53.958,26.565 r270 bottom (schematic designator C59)
C59_A2 "885012205086" WCAP-CSGP_0402_L1W0.5H0.5 158.958,26.615 r270 bottom (schematic designator C59)
C60_A1 "885012205086" WCAP-CSGP_0402_L1W0.5H0.5 52.464,26.565 r270 bottom (schematic designator C60)
C60_A2 "885012205086" WCAP-CSGP_0402_L1W0.5H0.5 157.464,26.615 r270 bottom (schematic designator C60)
C61_A1 "885012205086" WCAP-CSGP_0402_L1W0.5H0.5 50.971,26.565 r270 bottom (schematic designator C61)
C61_A2 "885012205086" WCAP-CSGP_0402_L1W0.5H0.5 155.971,26.615 r270 bottom (schematic designator C61)
C62_A1 "885012205086" WCAP-CSGP_0402_L1W0.5H0.5 55.451,26.565 r270 bottom (schematic designator C62)
C62_A2 "885012205086" WCAP-CSGP_0402_L1W0.5H0.5 160.451,26.615 r270 bottom (schematic designator C62)
C63_A1 "885012205086" WCAP-CSGP_0402_L1W0.5H0.5 49.477,26.565 r270 bottom (schematic designator C63)
C63_A2 "885012205086" WCAP-CSGP_0402_L1W0.5H0.5 154.477,26.615 r270 bottom (schematic designator C63)
C64_A1 "885012205086" WCAP-CSGP_0402_L1W0.5H0.5 44.997,26.565 r270 bottom (schematic designator C64)
C64_A2 "885012205086" WCAP-CSGP_0402_L1W0.5H0.5 149.997,26.615 r270 bottom (schematic designator C64)
C65_A1 "885012205086" WCAP-CSGP_0402_L1W0.5H0.5 47.984,26.565 r270 bottom (schematic designator C65)
C65_A2 "885012205086" WCAP-CSGP_0402_L1W0.5H0.5 152.984,26.615 r270 bottom (schematic designator C65)
C66_A1 "885012205086" WCAP-CSGP_0402_L1W0.5H0.5 46.491,26.565 r270 bottom (schematic designator C66)
C66_A2 "885012205086" WCAP-CSGP_0402_L1W0.5H0.5 151.491,26.615 r270 bottom (schematic designator C66)
C67_A1 "GCM155R71H104KE02D" 0402 51.718,17.497 r180 bottom value=0.1uF (schematic designator C67)
C67_A2 "GCM155R71H104KE02D" 0402 156.718,17.547 r180 bottom value=0.1uF (schematic designator C67)
C68_A1 "885012205086" WCAP-CSGP_0402_L1W0.5H0.5 54.664,26.422 r270 top (schematic designator C68)
C68_A2 "885012205086" WCAP-CSGP_0402_L1W0.5H0.5 159.664,26.472 r270 top (schematic designator C68)
C69_A1 "885012205086" WCAP-CSGP_0402_L1W0.5H0.5 53.403,26.422 r270 top (schematic designator C69)
C69_A2 "885012205086" WCAP-CSGP_0402_L1W0.5H0.5 158.403,26.472 r270 top (schematic designator C69)
C70_A1 "885342206006" WCAP-CSMH_0603_L1.6W0.8H0.8_Reflow 107.507,85.947 r270 bottom (schematic designator C70)
C70_A2 "885342206006" WCAP-CSMH_0603_L1.6W0.8H0.8_Reflow 212.507,85.997 r270 bottom (schematic designator C70)
C71_A1 "885342206006" WCAP-CSMH_0603_L1.6W0.8H0.8_Reflow 106.11,85.959 r270 bottom (schematic designator C71)
C71_A2 "885342206006" WCAP-CSMH_0603_L1.6W0.8H0.8_Reflow 211.11,86.009 r270 bottom (schematic designator C71)
C72_A1 "885012205086" WCAP-CSGP_0402_L1W0.5H0.5 52.162,26.422 r270 top (schematic designator C72)
C72_A2 "885012205086" WCAP-CSGP_0402_L1W0.5H0.5 157.162,26.472 r270 top (schematic designator C72)
C73_A1 "885012205086" WCAP-CSGP_0402_L1W0.5H0.5 56.387,26.393 r270 top (schematic designator C73)
C73_A2 "885012205086" WCAP-CSGP_0402_L1W0.5H0.5 161.387,26.443 r270 top (schematic designator C73)
C74_A1 "885012205085R" WCAP-CSGP_0402_L1W0.5H0.5 76.842,84.437 r270 bottom (schematic designator C74)
C74_A2 "885012205085R" WCAP-CSGP_0402_L1W0.5H0.5 181.842,84.487 r270 bottom (schematic designator C74)
C75_A1 "885342206006" WCAP-CSMH_0603_L1.6W0.8H0.8_Reflow 104.713,85.959 r270 bottom (schematic designator C75)
C75_A2 "885342206006" WCAP-CSMH_0603_L1.6W0.8H0.8_Reflow 209.713,86.009 r270 bottom (schematic designator C75)
C76_A1 "885012205086" WCAP-CSGP_0402_L1W0.5H0.5 50.832,26.422 r270 top (schematic designator C76)
C76_A2 "885012205086" WCAP-CSGP_0402_L1W0.5H0.5 155.832,26.472 r270 top (schematic designator C76)
C77_A1 "885012205086" WCAP-CSGP_0402_L1W0.5H0.5 46.781,26.422 r270 top (schematic designator C77)
C77_A2 "885012205086" WCAP-CSGP_0402_L1W0.5H0.5 151.781,26.472 r270 top (schematic designator C77)
C78_A1 "885012205085R" WCAP-CSGP_0402_L1W0.5H0.5 78.317,84.462 r270 bottom (schematic designator C78)
C78_A2 "885012205085R" WCAP-CSGP_0402_L1W0.5H0.5 183.317,84.512 r270 bottom (schematic designator C78)
C79_A1 "885342206006" WCAP-CSMH_0603_L1.6W0.8H0.8_Reflow 103.316,85.959 r270 bottom (schematic designator C79)
C79_A2 "885342206006" WCAP-CSMH_0603_L1.6W0.8H0.8_Reflow 208.316,86.009 r270 bottom (schematic designator C79)
C80_A1 "885012205086" WCAP-CSGP_0402_L1W0.5H0.5 49.482,26.422 r270 top (schematic designator C80)
C80_A2 "885012205086" WCAP-CSGP_0402_L1W0.5H0.5 154.482,26.472 r270 top (schematic designator C80)
C81_A1 "885012205086" WCAP-CSGP_0402_L1W0.5H0.5 48.127,26.422 r270 top (schematic designator C81)
C81_A2 "885012205086" WCAP-CSGP_0402_L1W0.5H0.5 153.127,26.472 r270 top (schematic designator C81)
C82_A1 "885012205085R" WCAP-CSGP_0402_L1W0.5H0.5 75.592,84.412 r270 bottom (schematic designator C82)
C82_A2 "885012205085R" WCAP-CSGP_0402_L1W0.5H0.5 180.592,84.462 r270 bottom (schematic designator C82)
C83_A1 "885342206006" WCAP-CSMH_0603_L1.6W0.8H0.8_Reflow 101.919,85.959 r270 bottom (schematic designator C83)
C83_A2 "885342206006" WCAP-CSMH_0603_L1.6W0.8H0.8_Reflow 206.919,86.009 r270 bottom (schematic designator C83)
C84_A1 "885012205085R" WCAP-CSGP_0402_L1W0.5H0.5 79.667,84.362 r270 bottom (schematic designator C84)
C84_A2 "885012205085R" WCAP-CSGP_0402_L1W0.5H0.5 184.667,84.412 r270 bottom (schematic designator C84)
C85_A1 "885342206006" WCAP-CSMH_0603_L1.6W0.8H0.8_Reflow 100.522,85.959 r270 bottom (schematic designator C85)
C85_A2 "885342206006" WCAP-CSMH_0603_L1.6W0.8H0.8_Reflow 205.522,86.009 r270 bottom (schematic designator C85)
C86_A1 "885012205085R" WCAP-CSGP_0402_L1W0.5H0.5 80.942,84.412 r270 bottom (schematic designator C86)
C86_A2 "885012205085R" WCAP-CSGP_0402_L1W0.5H0.5 185.942,84.462 r270 bottom (schematic designator C86)
C87_A1 "885342206006" WCAP-CSMH_0603_L1.6W0.8H0.8_Reflow 99.125,85.959 r270 bottom (schematic designator C87)
C87_A2 "885342206006" WCAP-CSMH_0603_L1.6W0.8H0.8_Reflow 204.125,86.009 r270 bottom (schematic designator C87)
C88_A1 "GCM155R71H104KE02D" 0402 53.103,24.373 r180 top value=0.1uF (schematic designator C88)
C88_A2 "GCM155R71H104KE02D" 0402 158.103,24.423 r180 top value=0.1uF (schematic designator C88)
C89_A1 "885012205085R" WCAP-CSGP_0402_L1W0.5H0.5 82.267,84.487 r270 bottom (schematic designator C89)
C89_A2 "885012205085R" WCAP-CSGP_0402_L1W0.5H0.5 187.267,84.537 r270 bottom (schematic designator C89)
C90_A1 "885342206006" WCAP-CSMH_0603_L1.6W0.8H0.8_Reflow 97.728,85.959 r270 bottom (schematic designator C90)
C90_A2 "885342206006" WCAP-CSMH_0603_L1.6W0.8H0.8_Reflow 202.728,86.009 r270 bottom (schematic designator C90)
C91_A1 "885012205062" WCAP-CSGP_0402_L1W0.5H0.5 78.087,33.886 r0 top (schematic designator C91)
C91_A2 "885012205062" WCAP-CSGP_0402_L1W0.5H0.5 183.087,33.936 r0 top (schematic designator C91)
C92_A1 "885012205085R" WCAP-CSGP_0402_L1W0.5H0.5 83.717,84.487 r270 bottom (schematic designator C92)
C92_A2 "885012205085R" WCAP-CSGP_0402_L1W0.5H0.5 188.717,84.537 r270 bottom (schematic designator C92)
C93_A1 "885342206006" WCAP-CSMH_0603_L1.6W0.8H0.8_Reflow 96.331,85.959 r270 bottom (schematic designator C93)
C93_A2 "885342206006" WCAP-CSMH_0603_L1.6W0.8H0.8_Reflow 201.331,86.009 r270 bottom (schematic designator C93)
C94_A1 "GCM155R71H104KE02D" 0402 58.455,26.461 r270 bottom value=0.1uF (schematic designator C94)
C94_A2 "GCM155R71H104KE02D" 0402 163.455,26.511 r270 bottom value=0.1uF (schematic designator C94)
C95_A1 "885012205085R" WCAP-CSGP_0402_L1W0.5H0.5 26.89,84.212 r270 bottom (schematic designator C95)
C95_A2 "885012205085R" WCAP-CSGP_0402_L1W0.5H0.5 131.89,84.262 r270 bottom (schematic designator C95)
C96_A1 "885342206006" WCAP-CSMH_0603_L1.6W0.8H0.8_Reflow 94.934,85.959 r270 bottom (schematic designator C96)
C96_A2 "885342206006" WCAP-CSMH_0603_L1.6W0.8H0.8_Reflow 199.934,86.009 r270 bottom (schematic designator C96)
C97_A1 "885012205062" WCAP-CSGP_0402_L1W0.5H0.5 77.031,34.984 r0 top (schematic designator C97)
C97_A2 "885012205062" WCAP-CSGP_0402_L1W0.5H0.5 182.031,35.034 r0 top (schematic designator C97)
C98_A1 "885012205085R" WCAP-CSGP_0402_L1W0.5H0.5 28.066,84.212 r270 bottom (schematic designator C98)
C98_A2 "885012205085R" WCAP-CSGP_0402_L1W0.5H0.5 133.066,84.262 r270 bottom (schematic designator C98)
C99_A1 "885342206006" WCAP-CSMH_0603_L1.6W0.8H0.8_Reflow 93.536,85.959 r270 bottom (schematic designator C99)
C99_A2 "885342206006" WCAP-CSMH_0603_L1.6W0.8H0.8_Reflow 198.536,86.009 r270 bottom (schematic designator C99)
C100_A1 "885012205062" WCAP-CSGP_0402_L1W0.5H0.5 76.01,33.886 r0 top (schematic designator C100)
C100_A2 "885012205062" WCAP-CSGP_0402_L1W0.5H0.5 181.01,33.936 r0 top (schematic designator C100)
C101_A1 "885012205062" WCAP-CSGP_0402_L1W0.5H0.5 86.559,23.154 r270 top (schematic designator C101)
C101_A2 "885012205062" WCAP-CSGP_0402_L1W0.5H0.5 191.559,23.204 r270 top (schematic designator C101)
C102_A1 "885012205085R" WCAP-CSGP_0402_L1W0.5H0.5 25.715,84.212 r270 bottom (schematic designator C102)
C102_A2 "885012205085R" WCAP-CSGP_0402_L1W0.5H0.5 130.715,84.262 r270 bottom (schematic designator C102)
C103_A1 "885342206006" WCAP-CSMH_0603_L1.6W0.8H0.8_Reflow 92.139,85.959 r270 bottom (schematic designator C103)
C103_A2 "885342206006" WCAP-CSMH_0603_L1.6W0.8H0.8_Reflow 197.139,86.009 r270 bottom (schematic designator C103)
C104_A1 "885012205085R" WCAP-CSGP_0402_L1W0.5H0.5 29.241,84.212 r270 bottom (schematic designator C104)
C104_A2 "885012205085R" WCAP-CSGP_0402_L1W0.5H0.5 134.241,84.262 r270 bottom (schematic designator C104)
C105_A1 "885342206006" WCAP-CSMH_0603_L1.6W0.8H0.8_Reflow 90.742,85.959 r270 bottom (schematic designator C105)
C105_A2 "885342206006" WCAP-CSMH_0603_L1.6W0.8H0.8_Reflow 195.742,86.009 r270 bottom (schematic designator C105)
C106_A1 "885012205062" WCAP-CSGP_0402_L1W0.5H0.5 74.956,34.979 r0 top (schematic designator C106)
C106_A2 "885012205062" WCAP-CSGP_0402_L1W0.5H0.5 179.956,35.028 r0 top (schematic designator C106)
C107_A1 "885012205062" WCAP-CSGP_0402_L1W0.5H0.5 85.446,24.173 r270 top (schematic designator C107)
C107_A2 "885012205062" WCAP-CSGP_0402_L1W0.5H0.5 190.446,24.223 r270 top (schematic designator C107)
C108_A1 "885012205085R" WCAP-CSGP_0402_L1W0.5H0.5 30.416,84.212 r270 bottom (schematic designator C108)
C108_A2 "885012205085R" WCAP-CSGP_0402_L1W0.5H0.5 135.416,84.262 r270 bottom (schematic designator C108)
C109_A1 "885342206006" WCAP-CSMH_0603_L1.6W0.8H0.8_Reflow 58.533,85.959 r270 bottom (schematic designator C109)
C109_A2 "885342206006" WCAP-CSMH_0603_L1.6W0.8H0.8_Reflow 163.533,86.009 r270 bottom (schematic designator C109)
C110_A1 "885012205062" WCAP-CSGP_0402_L1W0.5H0.5 73.947,33.879 r0 top (schematic designator C110)
C110_A2 "885012205062" WCAP-CSGP_0402_L1W0.5H0.5 178.947,33.929 r0 top (schematic designator C110)
C111_A1 "885012205062" WCAP-CSGP_0402_L1W0.5H0.5 86.559,25.124 r270 top (schematic designator C111)
C111_A2 "885012205062" WCAP-CSGP_0402_L1W0.5H0.5 191.559,25.174 r270 top (schematic designator C111)
C112_A1 "885012205085R" WCAP-CSGP_0402_L1W0.5H0.5 31.592,84.212 r270 bottom (schematic designator C112)
C112_A2 "885012205085R" WCAP-CSGP_0402_L1W0.5H0.5 136.592,84.262 r270 bottom (schematic designator C112)
C113_A1 "885342206006" WCAP-CSMH_0603_L1.6W0.8H0.8_Reflow 57.142,85.959 r270 bottom (schematic designator C113)
C113_A2 "885342206006" WCAP-CSMH_0603_L1.6W0.8H0.8_Reflow 162.142,86.009 r270 bottom (schematic designator C113)
C114_A1 "885012205085R" WCAP-CSGP_0402_L1W0.5H0.5 32.767,84.212 r270 bottom (schematic designator C114)
C114_A2 "885012205085R" WCAP-CSGP_0402_L1W0.5H0.5 137.767,84.262 r270 bottom (schematic designator C114)
C115_A1 "885342206006" WCAP-CSMH_0603_L1.6W0.8H0.8_Reflow 55.75,85.959 r270 bottom (schematic designator C115)
C115_A2 "885342206006" WCAP-CSMH_0603_L1.6W0.8H0.8_Reflow 160.75,86.009 r270 bottom (schematic designator C115)
C116_A1 "885012205062" WCAP-CSGP_0402_L1W0.5H0.5 72.894,34.974 r0 top (schematic designator C116)
C116_A2 "885012205062" WCAP-CSGP_0402_L1W0.5H0.5 177.894,35.024 r0 top (schematic designator C116)
C117_A1 "885012205062" WCAP-CSGP_0402_L1W0.5H0.5 85.445,26.169 r270 top (schematic designator C117)
C117_A2 "885012205062" WCAP-CSGP_0402_L1W0.5H0.5 190.445,26.219 r270 top (schematic designator C117)
C118_A1 "885012205085R" WCAP-CSGP_0402_L1W0.5H0.5 85.392,84.412 r270 bottom (schematic designator C118)
C118_A2 "885012205085R" WCAP-CSGP_0402_L1W0.5H0.5 190.392,84.462 r270 bottom (schematic designator C118)
C119_A1 "885342206006" WCAP-CSMH_0603_L1.6W0.8H0.8_Reflow 54.358,85.959 r270 bottom (schematic designator C119)
C119_A2 "885342206006" WCAP-CSMH_0603_L1.6W0.8H0.8_Reflow 159.358,86.009 r270 bottom (schematic designator C119)
C120_A1 "885012205062" WCAP-CSGP_0402_L1W0.5H0.5 71.857,33.884 r0 top (schematic designator C120)
C120_A2 "885012205062" WCAP-CSGP_0402_L1W0.5H0.5 176.857,33.934 r0 top (schematic designator C120)
C121_A1 "885012205062" WCAP-CSGP_0402_L1W0.5H0.5 86.559,27.119 r270 top (schematic designator C121)
C121_A2 "885012205062" WCAP-CSGP_0402_L1W0.5H0.5 191.559,27.169 r270 top (schematic designator C121)
C122_A1 "885012205062" WCAP-CSGP_0402_L1W0.5H0.5 85.441,22.213 r270 top (schematic designator C122)
C122_A2 "885012205062" WCAP-CSGP_0402_L1W0.5H0.5 190.441,22.263 r270 top (schematic designator C122)
C123_A1 "885342206006" WCAP-CSMH_0603_L1.6W0.8H0.8_Reflow 52.966,85.959 r270 bottom (schematic designator C123)
C123_A2 "885342206006" WCAP-CSMH_0603_L1.6W0.8H0.8_Reflow 157.966,86.009 r270 bottom (schematic designator C123)
C124_A1 "885012005057" WCAP-CSGP_0402_L1W0.5H0.5 64.547,15.089 r180 top (schematic designator C124)
C124_A2 "885012005057" WCAP-CSGP_0402_L1W0.5H0.5 169.547,15.139 r180 top (schematic designator C124)
C125_A1 "885342206006" WCAP-CSMH_0603_L1.6W0.8H0.8_Reflow 51.574,85.959 r270 bottom (schematic designator C125)
C125_A2 "885342206006" WCAP-CSMH_0603_L1.6W0.8H0.8_Reflow 156.574,86.009 r270 bottom (schematic designator C125)
C126_A1 "885012205062" WCAP-CSGP_0402_L1W0.5H0.5 70.833,34.999 r0 top (schematic designator C126)
C126_A2 "885012205062" WCAP-CSGP_0402_L1W0.5H0.5 175.833,35.049 r0 top (schematic designator C126)
C127_A1 "885012205062" WCAP-CSGP_0402_L1W0.5H0.5 85.441,28.217 r270 top (schematic designator C127)
C127_A2 "885012205062" WCAP-CSGP_0402_L1W0.5H0.5 190.441,28.267 r270 top (schematic designator C127)
C128_A1 "885012005057" WCAP-CSGP_0402_L1W0.5H0.5 65.772,21.722 r0 top (schematic designator C128)
C128_A2 "885012005057" WCAP-CSGP_0402_L1W0.5H0.5 170.772,21.772 r0 top (schematic designator C128)
C129_A1 "885342206006" WCAP-CSMH_0603_L1.6W0.8H0.8_Reflow 50.182,85.959 r270 bottom (schematic designator C129)
C129_A2 "885342206006" WCAP-CSMH_0603_L1.6W0.8H0.8_Reflow 155.182,86.009 r270 bottom (schematic designator C129)
C130_A1 "885012205062" WCAP-CSGP_0402_L1W0.5H0.5 65.48,32.16 r90 top (schematic designator C130)
C130_A2 "885012205062" WCAP-CSGP_0402_L1W0.5H0.5 170.48,32.21 r90 top (schematic designator C130)
C131_A1 "885012205062" WCAP-CSGP_0402_L1W0.5H0.5 86.559,29.183 r270 top (schematic designator C131)
C131_A2 "885012205062" WCAP-CSGP_0402_L1W0.5H0.5 191.559,29.233 r270 top (schematic designator C131)
C132_A1 "885342206006" WCAP-CSMH_0603_L1.6W0.8H0.8_Reflow 48.79,85.959 r270 bottom (schematic designator C132)
C132_A2 "885342206006" WCAP-CSMH_0603_L1.6W0.8H0.8_Reflow 153.79,86.009 r270 bottom (schematic designator C132)
C133_A1 "885342206006" WCAP-CSMH_0603_L1.6W0.8H0.8_Reflow 47.398,85.959 r270 bottom (schematic designator C133)
C133_A2 "885342206006" WCAP-CSMH_0603_L1.6W0.8H0.8_Reflow 152.398,86.009 r270 bottom (schematic designator C133)
C134_A1 "885342206006" WCAP-CSMH_0603_L1.6W0.8H0.8_Reflow 46.007,85.959 r270 bottom (schematic designator C134)
C134_A2 "885342206006" WCAP-CSMH_0603_L1.6W0.8H0.8_Reflow 151.007,86.009 r270 bottom (schematic designator C134)
C135_A1 "885342206006" WCAP-CSMH_0603_L1.6W0.8H0.8_Reflow 44.615,85.959 r270 bottom (schematic designator C135)
C135_A2 "885342206006" WCAP-CSMH_0603_L1.6W0.8H0.8_Reflow 149.615,86.009 r270 bottom (schematic designator C135)
C136_A1 "885012205062" WCAP-CSGP_0402_L1W0.5H0.5 64.275,31.046 r90 top (schematic designator C136)
C136_A2 "885012205062" WCAP-CSGP_0402_L1W0.5H0.5 169.275,31.096 r90 top (schematic designator C136)
C137_A1 "885012205062" WCAP-CSGP_0402_L1W0.5H0.5 85.433,30.278 r270 top (schematic designator C137)
C137_A2 "885012205062" WCAP-CSGP_0402_L1W0.5H0.5 190.433,30.328 r270 top (schematic designator C137)
C138_A1 "885012005059" WCAP-CSGP_0402_L1W0.5H0.5 77.657,16.76 r180 bottom (schematic designator C138)
C138_A2 "885012005059" WCAP-CSGP_0402_L1W0.5H0.5 182.657,16.81 r180 bottom (schematic designator C138)
C139_A1 "885012005059" WCAP-CSGP_0402_L1W0.5H0.5 82.079,19.959 r0 bottom (schematic designator C139)
C139_A2 "885012005059" WCAP-CSGP_0402_L1W0.5H0.5 187.079,20.009 r0 bottom (schematic designator C139)
C140_A1 "885342206006" WCAP-CSMH_0603_L1.6W0.8H0.8_Reflow 43.223,85.959 r270 bottom (schematic designator C140)
C140_A2 "885342206006" WCAP-CSMH_0603_L1.6W0.8H0.8_Reflow 148.223,86.009 r270 bottom (schematic designator C140)
C141_A1 "885342206006" WCAP-CSMH_0603_L1.6W0.8H0.8_Reflow 41.831,85.959 r270 bottom (schematic designator C141)
C141_A2 "885342206006" WCAP-CSMH_0603_L1.6W0.8H0.8_Reflow 146.831,86.009 r270 bottom (schematic designator C141)
C142_A1 "GCM155R71H104KE02D" 0402 10.033,36.666 r0 top value=0.1uF (schematic designator C142)
C142_A2 "GCM155R71H104KE02D" 0402 122.419,9.671 r90 top value=0.1uF (schematic designator C142)
C143_A1 "GCM155R71H104KE02D" 0402 99.708,9.621 r90 top value=0.1uF (schematic designator C143)
C143_A2 "GCM155R71H104KE02D" 0402 234.331,36.692 r180 top value=0.1uF (schematic designator C143)
C144_A1 "885012205062" WCAP-CSGP_0402_L1W0.5H0.5 65.48,30.107 r90 top (schematic designator C144)
C144_A2 "885012205062" WCAP-CSGP_0402_L1W0.5H0.5 170.48,30.157 r90 top (schematic designator C144)
C145_A1 "885012205062" WCAP-CSGP_0402_L1W0.5H0.5 82.19,33.863 r0 top (schematic designator C145)
C145_A2 "885012205062" WCAP-CSGP_0402_L1W0.5H0.5 187.19,33.913 r0 top (schematic designator C145)
C146_A1 "885342206006" WCAP-CSMH_0603_L1.6W0.8H0.8_Reflow 40.439,85.959 r270 bottom (schematic designator C146)
C146_A2 "885342206006" WCAP-CSMH_0603_L1.6W0.8H0.8_Reflow 145.439,86.009 r270 bottom (schematic designator C146)
C147_A1 "885012005059" WCAP-CSGP_0402_L1W0.5H0.5 99.075,11.636 r180 top (schematic designator C147)
C147_A2 "885012005059" WCAP-CSGP_0402_L1W0.5H0.5 232.316,36.059 r270 top (schematic designator C147)
C148_A1 "885012005059" WCAP-CSGP_0402_L1W0.5H0.5 12.096,36.499 r90 top (schematic designator C148)
C148_A2 "885012005059" WCAP-CSGP_0402_L1W0.5H0.5 122.585,11.735 r180 top (schematic designator C148)
C149_A1 "885012005059" WCAP-CSGP_0402_L1W0.5H0.5 7.717,36.415 r90 top (schematic designator C149)
C149_A2 "885012005059" WCAP-CSGP_0402_L1W0.5H0.5 122.669,7.355 r180 top (schematic designator C149)
C150_A1 "885012005059" WCAP-CSGP_0402_L1W0.5H0.5 77.631,17.85 r0 bottom (schematic designator C150)
C150_A2 "885012005059" WCAP-CSGP_0402_L1W0.5H0.5 182.631,17.9 r0 bottom (schematic designator C150)
C151_A1 "885012005059" WCAP-CSGP_0402_L1W0.5H0.5 82.044,17.772 r180 bottom (schematic designator C151)
C151_A2 "885012005059" WCAP-CSGP_0402_L1W0.5H0.5 187.044,17.822 r180 bottom (schematic designator C151)
C152_A1 "885012205062" WCAP-CSGP_0402_L1W0.5H0.5 64.275,28.968 r90 top (schematic designator C152)
C152_A2 "885012205062" WCAP-CSGP_0402_L1W0.5H0.5 169.275,29.018 r90 top (schematic designator C152)
C153_A1 "885012205062" WCAP-CSGP_0402_L1W0.5H0.5 81.16,34.998 r0 top (schematic designator C153)
C153_A2 "885012205062" WCAP-CSGP_0402_L1W0.5H0.5 186.16,35.048 r0 top (schematic designator C153)
C154_A1 "885012005059" WCAP-CSGP_0402_L1W0.5H0.5 98.825,7.612 r0 top (schematic designator C154)
C154_A2 "885012005059" WCAP-CSGP_0402_L1W0.5H0.5 236.341,35.809 r90 top (schematic designator C154)
C155_A1 "885012205092" WCAP-CSGP_0402_L1W0.5H0.5 60.983,19.959 r0 top (schematic designator C155)
C155_A2 "885012205092" WCAP-CSGP_0402_L1W0.5H0.5 165.983,20.009 r0 top (schematic designator C155)
C156_A1 "885012205062" WCAP-CSGP_0402_L1W0.5H0.5 65.48,28.054 r90 top (schematic designator C156)
C156_A2 "885012205062" WCAP-CSGP_0402_L1W0.5H0.5 170.48,28.104 r90 top (schematic designator C156)
C157_A1 "885012205062" WCAP-CSGP_0402_L1W0.5H0.5 80.139,33.886 r0 top (schematic designator C157)
C157_A2 "885012205062" WCAP-CSGP_0402_L1W0.5H0.5 185.139,33.936 r0 top (schematic designator C157)
C158_A1 "GRM155C81C105KE11D" FP-GRM155C81C105KE11D_0402-MFG 58.502,24.162 r180 bottom value=1µF (schematic designator C158)
C158_A2 "GRM155C81C105KE11D" FP-GRM155C81C105KE11D_0402-MFG 163.502,24.212 r180 bottom value=1µF (schematic designator C158)
C159_A1 "GRM155C81C105KE11D" FP-GRM155C81C105KE11D_0402-MFG 58.507,18.454 r0 bottom value=1µF (schematic designator C159)
C159_A2 "GRM155C81C105KE11D" FP-GRM155C81C105KE11D_0402-MFG 163.455,18.501 r0 bottom value=1µF (schematic designator C159)
C160_A1 "GCM155R71H104KE02D" 0402 60.428,12.478 r90 top value=0.1uF (schematic designator C160)
C160_A2 "GCM155R71H104KE02D" 0402 165.428,12.528 r90 top value=0.1uF (schematic designator C160)
C161_A1 "GCM155R71H104KE02D" 0402 60.428,15.157 r90 top value=0.1uF (schematic designator C161)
